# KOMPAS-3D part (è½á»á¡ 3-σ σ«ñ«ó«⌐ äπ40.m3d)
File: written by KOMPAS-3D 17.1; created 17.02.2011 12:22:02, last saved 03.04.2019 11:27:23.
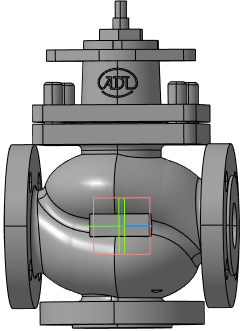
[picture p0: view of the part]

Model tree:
1. Плоскость XY
2. Плоскость ZX
3. Плоскость ZY
4. Ось X
5. Ось Y
6. Ось Z
7. Начало координат
8. Операция без истории:2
